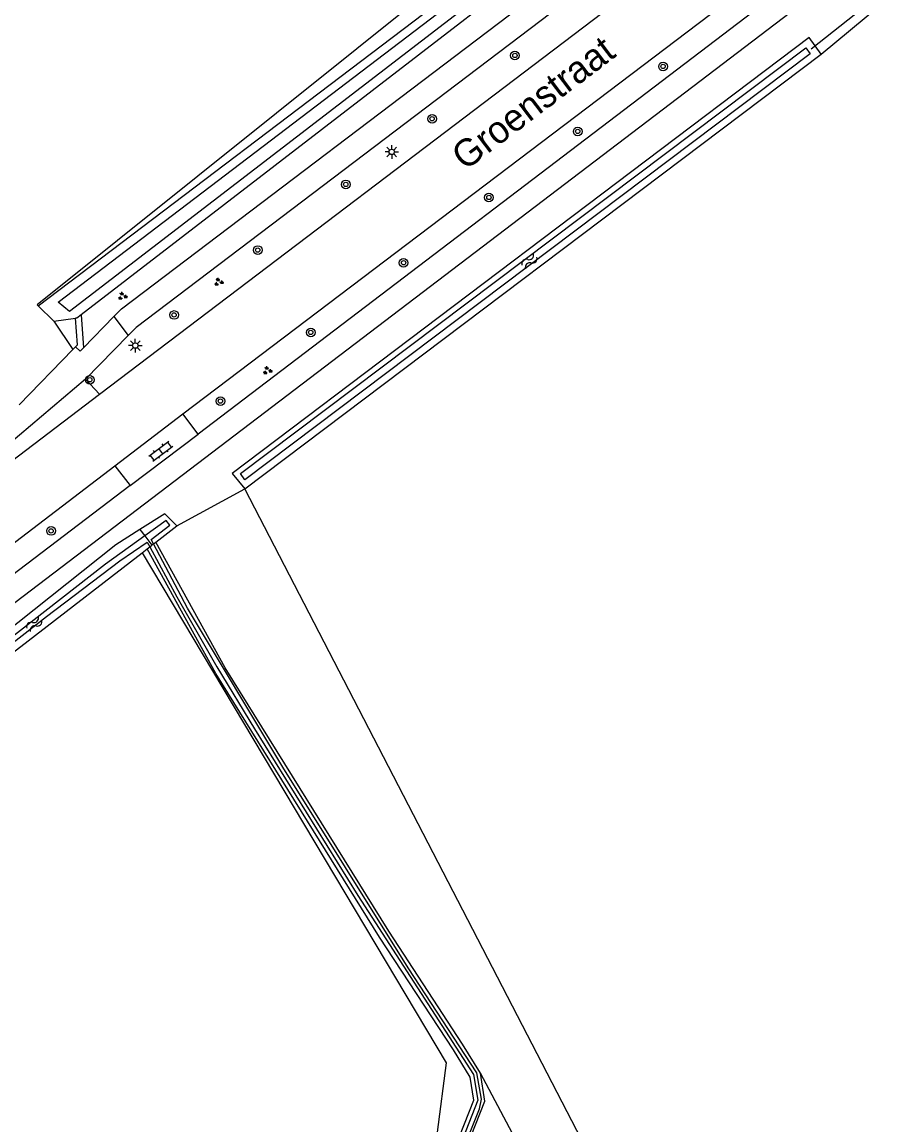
# Model space of a CAD drawing. Extents: x 137000 to 140001, y 403500 to 406000.
# Drawn here: x 139323.1 to 139404, y 403688.4 to 403790.2 of the extents above; entities that cross this region are included whole.
import ezdxf

# ---------------------------------------------------------------- set-up
doc = ezdxf.new("R2010")
doc.units = 0
for name, color, linetype in [('gg-anno-openbare ruimte label', 7, 'Continuous'), ('gg-knt-bronhoudergrens', 7, 'Continuous'), ('gg-knt-verharding', 7, 'Continuous'), ('gg-kntw-bovenkant insteek waterloop', 7, 'Continuous'), ('gg-kntw-waterlijn', 7, 'Continuous'), ('gg-kwrk-duiker nz buis', 7, 'Continuous'), ('gt-grn-groengrens', 7, 'Continuous'), ('gt-grn-vlakafsluiter', 7, 'Continuous'), ('gt-grn-weggrens', 7, 'Continuous'), ('gt-symb-boom', 7, 'Continuous'), ('gt-symb-groenvak', 7, 'Continuous'), ('gt-symb-klinker verharding', 7, 'Continuous'), ('gt-symb-lichtmast', 7, 'Continuous'), ('gt-symb-watersymbool', 7, 'Continuous')]:
    doc.layers.add(name, color=color, linetype=linetype)

# ---------------------------------------------------------------- blocks, each defined once
blk = doc.blocks.new('gt0-BOOM')
at = {"layer": 'gt-symb-boom'}
for radius in [0.4, 0.2]:
    blk.add_circle((0, 0), radius, dxfattribs=at)
blk = doc.blocks.new('gt0-WA')
at = {"layer": 'gt-symb-watersymbool'}
for centre, start, end in [((-0.32, 0.02), 28.0725, 151.9275), ((0.43, 0.42), 208.0725, 331.9275), ((-0.32, -0.43), 28.0725, 151.9275), ((0.43, -0.03), 208.0725, 331.9275)]:
    blk.add_arc(centre, 0.425, start, end, dxfattribs=at)
blk = doc.blocks.new('gt0-KL1')
at = {"layer": 'gt-symb-klinker verharding'}
for p, q in [((-1.15, 0.3), (1.15, 0.3)), ((-1, -0.3), (-1, 0.3)), ((-0.5, 0.3), (-0.5, 0.45)), ((0, -0.3), (0, 0.3)), ((0.5, 0.3), (0.5, 0.45)), ((1, -0.3), (1, 0.3)), ((-1.15, -0.3), (1.15, -0.3)), ((-0.5, -0.45), (-0.5, -0.3)), ((0.5, -0.45), (0.5, -0.3))]:
    blk.add_line(p, q, dxfattribs=at)
blk = doc.blocks.new('gt0-GRVAK')
at = {"layer": 'gt-symb-groenvak'}
for p, q in [((-0.11, 0.19), (-0.23, 0.24)), ((-0.18, 0.15), (0.09, 0.15)), ((-0.09, 0.21), (-0.16, 0.32)), ((-0.05, 0.21), (-0.05, 0.39)), ((0, 0.21), (0.06, 0.32)), ((0.01, 0.19), (0.13, 0.24)), ((0.26, -0.05), (0.2, 0.06)), ((0.3, -0.05), (0.3, 0.13)), ((0.35, -0.05), (0.41, 0.06)), ((-0.24, -0.23), (-0.36, -0.18)), ((-0.32, -0.26), (-0.05, -0.26)), ((-0.23, -0.21), (-0.29, -0.09)), ((-0.18, -0.2), (-0.18, -0.02)), ((-0.14, -0.21), (-0.07, -0.09)), ((-0.12, -0.23), (0, -0.18)), ((0.24, -0.07), (0.12, -0.02)), ((0.17, -0.11), (0.44, -0.11)), ((0.37, -0.07), (0.49, -0.02))]:
    blk.add_line(p, q, dxfattribs=at)
blk = doc.blocks.new('gt0-LMAST')
at = {"layer": 'gt-symb-lichtmast'}
for p, q in [((-0.18, 0.17), (-0.45, 0.44)), ((-0.01, 0.25), (-0.01, 0.62)), ((0.17, 0.17), (0.44, 0.44)), ((-0.26, 0), (-0.63, 0)), ((-0.18, -0.18), (-0.45, -0.45)), ((-0.01, -0.25), (-0.01, -0.63)), ((0.44, -0.45), (0.17, -0.18)), ((0.24, 0), (0.62, 0))]:
    blk.add_line(p, q, dxfattribs=at)
blk.add_circle((-0.01, 0), 0.25, dxfattribs=at)

msp = doc.modelspace()

# ---------------------------------------------------------------- linework, layer by layer
at = {"layer": 'gg-knt-bronhoudergrens'}
for p, q in [((139414.13, 403610.9), (139343.65, 403747.14)), ((139411.44, 403606.77), (139365.41, 403693.17))]:
    msp.add_line(p, q, dxfattribs=at)
msp.add_lwpolyline([(139334.15, 403741.23), (139362.23, 403694.12), (139360.56, 403681.34), (139352.56, 403659.25), (139348.3, 403651.39), (139340.15, 403638.81), (139307.18, 403603.11), (139302.8, 403605.9), (139242.69, 403671.72)], dxfattribs=at)
at = {"layer": 'gg-knt-verharding'}
for p, q in [((139330.22, 403755.87), (139403.26, 403811.28)), ((139337.92, 403754.06), (139390.66, 403794.02)), ((139392.01, 403792.27), (139339.33, 403752.19)), ((139328.53, 403763.21), (139328.74, 403760.16)), ((139328.74, 403760.16), (139331.56, 403763.04)), ((139331.56, 403763.04), (139332.88, 403761.28)), ((139328.93, 403757.24), (139332.88, 403761.28)), ((139327.77, 403760), (139328.01, 403760.25)), ((139322.79, 403754.88), (139327.77, 403760)), ((139330.22, 403755.87), (139328.93, 403757.24)), ((139310.85, 403741.17), (139330.22, 403755.87)), ((139331.64, 403749.24), (139337.92, 403754.06)), ((139339.33, 403752.19), (139337.92, 403754.06)), ((139333.05, 403747.44), (139339.33, 403752.19)), ((139308.19, 403731.4), (139331.64, 403749.24)), ((139331.64, 403749.24), (139333.05, 403747.44)), ((139333.05, 403747.44), (139309.61, 403729.61))]:
    msp.add_line(p, q, dxfattribs=at)
for points in [[(139462.76, 403843.55), (139455.99, 403838.49), (139429.35, 403818.02), (139335.78, 403746.78), (139191.52, 403637.05)], [(139331.56, 403763.04), (139332.24, 403763.74), (139409.76, 403822.49)], [(139401.53, 403813.55), (139333.6, 403762.02), (139332.88, 403761.28)], [(139328.01, 403760.25), (139328.18, 403760.43), (139328, 403762.88)], [(139328.01, 403760.25), (139328.43, 403759.85), (139328.74, 403760.16)]]:
    msp.add_lwpolyline(points, dxfattribs=at)
at = {"layer": 'gg-kntw-bovenkant insteek waterloop'}
for p, q in [((139324.56, 403764.02), (139398.25, 403819.95)), ((139343.65, 403747.14), (139396.87, 403787.27)), ((139324.56, 403764.02), (139326.01, 403762.62)), ((139326.01, 403762.62), (139328, 403762.88)), ((139335.42, 403742.21), (139337.35, 403743.7)), ((139311.71, 403723.9), (139334.15, 403741.23)), ((139334.15, 403741.23), (139334.62, 403741.59))]:
    msp.add_line(p, q, dxfattribs=at)
for points in [[(139398.25, 403819.95), (139399.78, 403818.07), (139328.53, 403763.21)], [(139396.87, 403787.27), (139395.76, 403788.81), (139342.47, 403748.54), (139343.65, 403747.14)], [(139328.53, 403763.21), (139328.13, 403762.9), (139328, 403762.88)], [(139337.35, 403743.7), (139336.27, 403744.82), (139333.96, 403743.36)], [(139333.96, 403743.36), (139331.73, 403741.95), (139310.58, 403725.14), (139311.71, 403723.9)], [(139365.41, 403693.17), (139363.74, 403695.86), (139356.93, 403706.28), (139341.82, 403730.59), (139335.42, 403742.21)], [(139307.11, 403600.09), (139310.45, 403604.07), (139320.9, 403615.1), (139327.41, 403622.16), (139336.97, 403632.62), (139342.95, 403639.97), (139347.74, 403647.17), (139352.81, 403659.43), (139356.38, 403669.39), (139364.79, 403690.69), (139364.46, 403692.81), (139362.9, 403695.32), (139356.08, 403705.74), (139340.96, 403730.08), (139334.62, 403741.59)], [(139307.6, 403599.11), (139311.2, 403603.4), (139321.63, 403614.42), (139328.14, 403621.48), (139337.73, 403631.97), (139343.76, 403639.38), (139348.62, 403646.7), (139353.74, 403659.07), (139357.32, 403669.04), (139365.82, 403690.58), (139365.41, 403693.17)]]:
    msp.add_lwpolyline(points, dxfattribs=at)
at = {"layer": 'gg-kntw-waterlijn'}
for points in [[(139326.4, 403764.37), (139397.89, 403818.77), (139398.44, 403818.05), (139327.46, 403763.49), (139326.4, 403764.37)], [(139343.24, 403748.53), (139395.45, 403787.85), (139395.86, 403787.3), (139343.64, 403747.96), (139343.24, 403748.53)], [(139335.21, 403742.05), (139334.99, 403742.45), (139336.73, 403743.78), (139336.39, 403744.22), (139334.41, 403742.79)], [(139334.41, 403742.79), (139330.78, 403740.18), (139311.68, 403725.32), (139311.98, 403724.95), (139325.34, 403735.35), (139332.1, 403740.49), (139334.61, 403742.22), (139334.86, 403741.78)], [(139334.86, 403741.78), (139337.36, 403737.15), (139341.05, 403730.68), (139344.53, 403724.97), (139354.08, 403709.58), (139364.76, 403693.07), (139365.15, 403690.68), (139361.77, 403682.04), (139357.32, 403670.93), (139352.96, 403658.97), (139348.04, 403647.01), (139343.04, 403639.49), (139336.66, 403631.68), (139315.41, 403608.73), (139310.64, 403603.71), (139307.24, 403599.83)], [(139307.47, 403599.37), (139312, 403604.72), (139320.41, 403613.55), (139337.32, 403631.92), (139343.5, 403639.48), (139348.41, 403646.85), (139353.67, 403659.69), (139356.47, 403667.47), (139359.16, 403674.52), (139365.3, 403689.87), (139365.5, 403690.78), (139365.06, 403693.2), (139358.74, 403702.91), (139347.15, 403721.42), (139338.35, 403736.1), (139335.21, 403742.05)]]:
    msp.add_lwpolyline(points, dxfattribs=at)
at = {"layer": 'gg-kwrk-duiker nz buis'}
msp.add_line((139402.22, 403792.7), (139395.95, 403787.71), dxfattribs=at)
at = {"layer": 'gt-grn-groengrens'}
for p, q in [((139396.87, 403787.27), (139402.28, 403791.75)), ((139326.01, 403762.62), (139327.77, 403760)), ((139337.35, 403743.7), (139343.65, 403747.14))]:
    msp.add_line(p, q, dxfattribs=at)
msp.add_lwpolyline([(139403.44, 403825.24), (139361.4, 403793.72), (139324.47, 403764.11), (139324.56, 403764.02)], dxfattribs=at)
at = {"layer": 'gt-grn-vlakafsluiter'}
for p, q in [((139333.96, 403743.36), (139334.41, 403742.79)), ((139334.41, 403742.79), (139335.07, 403741.94)), ((139334.62, 403741.59), (139334.86, 403741.78)), ((139334.86, 403741.78), (139335.07, 403741.94)), ((139335.21, 403742.05), (139335.07, 403741.94)), ((139335.21, 403742.05), (139335.42, 403742.21))]:
    msp.add_line(p, q, dxfattribs=at)
at = {"layer": 'gt-grn-weggrens'}
msp.add_line((139328.93, 403757.24), (139310.49, 403741.65), dxfattribs=at)

# ---------------------------------------------------------------- block references
at = {"layer": 'gt-symb-boom'}
for p in [(139368.58, 403787.14), (139382.26, 403786.13), (139360.94, 403781.3), (139374.38, 403780.13), (139352.97, 403775.24), (139366.18, 403774.03), (139344.84, 403769.18), (139358.3, 403768), (139337.11, 403763.18), (139349.73, 403761.57), (139329.33, 403757.2), (139341.39, 403755.23), (139325.75, 403743.24)]:
    msp.add_blockref('gt0-BOOM', p, dxfattribs=at)
at = {"layer": 'gt-symb-groenvak'}
for p in [(139341.22, 403766.22), (139332.34, 403764.92), (139345.72, 403758.05)]:
    msp.add_blockref('gt0-GRVAK', p, dxfattribs=at)
at = {"layer": 'gt-symb-klinker verharding', "rotation": 37.282255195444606}
msp.add_blockref('gt0-KL1', (139335.89, 403750.61), dxfattribs=at)
at = {"layer": 'gt-symb-lichtmast'}
for p in [(139357.22, 403778.24), (139333.54, 403760.36)]:
    msp.add_blockref('gt0-LMAST', p, dxfattribs=at)
at = {"layer": 'gt-symb-watersymbool'}
for p, rotation in [((139369.88, 403768.11), 45.1620809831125), ((139324.16, 403734.6), 45.162080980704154)]:
    msp.add_blockref('gt0-WA', p, dxfattribs=dict(at, rotation=rotation))

# ---------------------------------------------------------------- texts
at = {"layer": 'gg-anno-openbare ruimte label'}
msp.add_text('Groenstraat', height=2.5, rotation=37.2, dxfattribs=at).set_placement((139363.98, 403776.45))

doc.saveas('drawing.dxf')
